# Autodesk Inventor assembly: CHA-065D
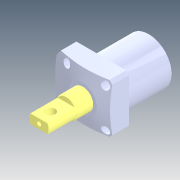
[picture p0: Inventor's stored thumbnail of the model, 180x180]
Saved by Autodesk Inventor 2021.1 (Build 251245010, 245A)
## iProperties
Created: 2018-07
Part Number: CHA-065D
Description: STEP AP214
Document SubType Name: Assembly
Designer: user
Title: CHA-065D(Ë«±Û£©.STEP
Revision Number: ÈÎºÎ
Sending System: SolidWorks 2016
Preprocessor: SwSTEP 2.0
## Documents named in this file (3)
- D:\Vault_2016\Projekty\Clamptek\Hydraulic\CHA\CHA\CHA-065\Inventor\CHA-065D\CHA-065D.iam
- D:\Vault_2016\Projekty\Clamptek\Hydraulic\CHA\CHA\CHA-065\Inventor\CHA-065D\CHA-065BT.ipt
- D:\Vault_2016\Projekty\Clamptek\Hydraulic\CHA\CHA\CHA-065\Inventor\CHA-065D\CHA-065D(Ë«±Û£©»îÈû¸Ë.ipt
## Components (2 placed, 2 different names)
1. CHA-065BT_1
2. CHA-065D(Ë«±Û£©»îÈû¸Ë_2
